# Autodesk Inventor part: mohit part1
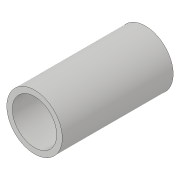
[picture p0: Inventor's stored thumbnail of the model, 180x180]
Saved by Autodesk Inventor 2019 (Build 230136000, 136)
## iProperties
Created: 2020-02
Part Number: mohit part1
Material: Generic
Document SubType Name: Modeling
Designer: Mahabaleshwarppa
Density: 1 g/cm^3
Appearance: Default
Author: Mahabaleshwarppa
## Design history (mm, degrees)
sketch "Sketch1"
  geometry: C1 r 2.5 at (0, 0); 1 further point
  constraints: 1 centre point, 1 coincident
  dimensions: "d0" = 5 diameter of C1
extrude "Extrusion1" new body sketch "Sketch1" distance "d1" = 10; taper "d2" = 0 deg
sketch "Sketch2"
  geometry: C1 r 2 at (0, 0); 1 further point
  constraints: 1 centre point, 1 coincident
  dimensions: "d3" = 4 diameter of C1
extrude "Extrusion2" cut sketch "Sketch2" extent not by distance; stored distance "d4" = 0; taper "d5" = 0 deg
body "Solid1"
